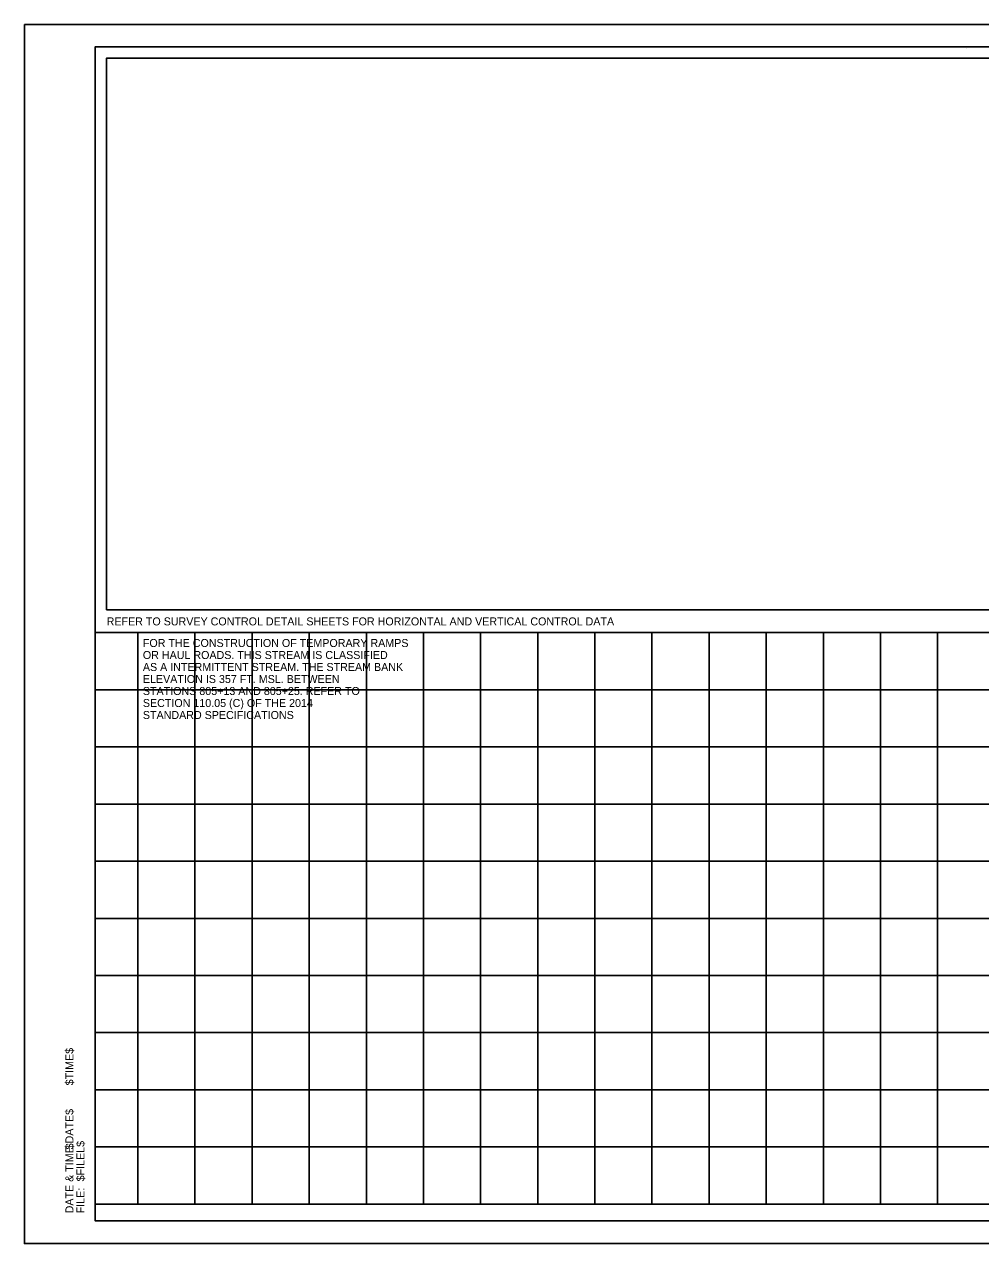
# Model space of a CAD drawing. Extents: x 816090 to 819714, y 1801340 to 1803641.
# Drawn here: x 818048 to 818885, y 1801340 to 1802407 of the extents above; entities that cross this region are included whole.
import ezdxf

# ---------------------------------------------------------------- set-up
doc = ezdxf.new("R2010")
doc.units = 0
for name, color, linetype in [('R_Border', 7, 'Continuous'), ('R_Border Notes', 7, 'Continuous'), ('R_BORDER SURVEY NOTE', 7, 'Continuous'), ('R_No Plot', 7, 'Continuous')]:
    doc.layers.add(name, color=color, linetype=linetype)

msp = doc.modelspace()

# ---------------------------------------------------------------- linework, layer by layer
at = {"layer": 'R_Border'}
for p, q in [((818109.6, 1802387.1), (819690.5, 1802387.1)), ((818109.6, 1801359.8), (818109.6, 1802387.1)), ((818872.2, 1802385.8), (818872.2, 1802385.8)), ((818872.2, 1802385.8), (818872.2, 1802385.8)), ((819690.5, 1801874.5), (818109.6, 1801874.5)), ((818146.9, 1801374.5), (818146.9, 1801874.5)), ((818196.9, 1801374.5), (818196.9, 1801874.5)), ((818246.9, 1801374.5), (818246.9, 1801874.5)), ((818296.9, 1801374.5), (818296.9, 1801874.5)), ((818346.9, 1801374.5), (818346.9, 1801874.5)), ((818396.9, 1801374.5), (818396.9, 1801874.5)), ((818446.9, 1801374.5), (818446.9, 1801874.5)), ((818496.9, 1801374.5), (818496.9, 1801874.5)), ((818546.9, 1801374.5), (818546.9, 1801874.5)), ((818596.9, 1801374.5), (818596.9, 1801874.5)), ((818646.9, 1801374.5), (818646.9, 1801874.5)), ((818696.9, 1801374.5), (818696.9, 1801874.5)), ((818746.9, 1801374.5), (818746.9, 1801874.5)), ((818796.9, 1801374.5), (818796.9, 1801874.5)), ((818846.9, 1801374.5), (818846.9, 1801874.5)), ((819690.5, 1801824.5), (818109.6, 1801824.5)), ((819690.5, 1801774.5), (818109.6, 1801774.5)), ((819690.5, 1801724.5), (818109.6, 1801724.5)), ((819690.5, 1801674.5), (818109.6, 1801674.5)), ((819690.5, 1801624.5), (818109.6, 1801624.5)), ((819690.5, 1801574.5), (818109.6, 1801574.5)), ((819690.5, 1801524.5), (818109.6, 1801524.5)), ((819690.5, 1801474.5), (818109.6, 1801474.5)), ((819690.5, 1801424.5), (818109.6, 1801424.5)), ((819690.5, 1801374.5), (818109.6, 1801374.5)), ((818109.6, 1801359.8), (818109.6, 1801359.8)), ((819690.5, 1801359.8), (818109.6, 1801359.8))]:
    msp.add_line(p, q, dxfattribs=at)
at = {"layer": 'R_No Plot'}
for p, q in [((818047.6, 1802406.6), (819714.3, 1802406.6)), ((818047.6, 1801339.9), (819714.3, 1801339.9))]:
    msp.add_line(p, q, dxfattribs=at)
for points in [[(818047.6, 1802406.6), (819714.3, 1802406.6), (819714.3, 1801339.9), (818047.6, 1801339.9)], [(819377.3, 1802387.1), (819377.3, 1802337.7), (819457.8, 1802337.7), (819576.4, 1802337.7), (819576.4, 1802227.7), (819690.5, 1802227.7), (819690.5, 1801874.5), (818109.6, 1801874.5), (818109.6, 1802387.1)], [(819680.5, 1801894.5), (818119.6, 1801894.5), (818119.6, 1802377.1), (819367.3, 1802377.1), (819367.3, 1802327.7), (819576.4, 1802327.7), (819576.4, 1802227.7), (819680.5, 1802227.7)], [(819680.5, 1801894.5), (818119.6, 1801894.5), (818119.6, 1802377.1), (819367.3, 1802377.1), (819367.3, 1802327.7), (819576.4, 1802327.7), (819576.4, 1802227.7), (819680.5, 1802227.7)], [(819680.5, 1801894.5), (818119.6, 1801894.5), (818119.6, 1802377.1), (819367.3, 1802377.1), (819367.3, 1802327.7), (819576.4, 1802327.7), (819576.4, 1802227.7), (819680.5, 1802227.7)], [(818109.6, 1801874.5), (819690.5, 1801874.5), (819690.5, 1801359.8), (818109.6, 1801359.8)], [(818109.6, 1801874.5), (819690.5, 1801874.5), (819690.5, 1801359.8), (818109.6, 1801359.8)]]:
    msp.add_lwpolyline(points, close=True, dxfattribs=at)

# ---------------------------------------------------------------- texts
at = {"layer": 'R_Border Notes'}
for s, p in [('$TIME$', (818090.5, 1801478.4)), ('$DATE$', (818090.5, 1801422.4)), ('DATE & TIME:', (818090.5, 1801366.4)), ('$FILEL$', (818100.2, 1801394.4)), ('FILE: ', (818100.2, 1801366.4))]:
    msp.add_text(s, height=7, rotation=90, dxfattribs=at).set_placement(p)
at = {"layer": 'R_BORDER SURVEY NOTE'}
for s, p in [('REFER TO SURVEY CONTROL DETAIL SHEETS FOR HORIZONTAL AND VERTICAL CONTROL DATA', (818119.6, 1801880.8)), ('FOR THE CONSTRUCTION OF TEMPORARY RAMPS', (818151.3, 1801861.9)), ('OR HAUL ROADS. THIS STREAM IS CLASSIFIED', (818151.3, 1801851.4)), ('AS A INTERMITTENT STREAM. THE STREAM BANK', (818151.3, 1801840.9)), ('ELEVATION IS 357 FT. MSL. BETWEEN ', (818151.3, 1801830.4)), ('STATIONS 805+13 AND 805+25. REFER TO', (818151.3, 1801819.9)), ('SECTION 110.05 (C) OF THE 2014 ', (818151.3, 1801809.4)), ('STANDARD SPECIFICATIONS', (818151.3, 1801798.9))]:
    msp.add_text(s, height=7, dxfattribs=at).set_placement(p)

doc.saveas('drawing.dxf')
